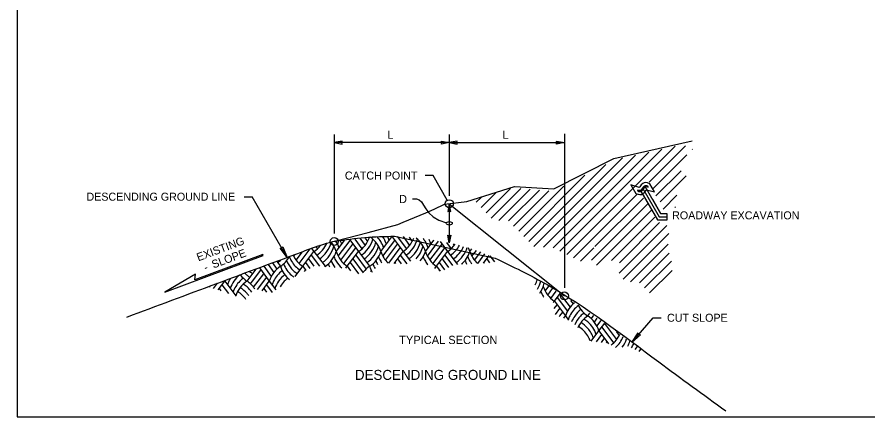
# Model space of a CAD drawing. Extents: x 99862 to 103151, y 100000 to 102076.
# Drawn here: x 99862 to 101562, y 100000 to 100799 of the extents above; entities that cross this region are included whole.
import ezdxf

# ---------------------------------------------------------------- set-up
doc = ezdxf.new("R2010")
doc.units = 0
for name, color, linetype in [('Level 1', 7, 'Continuous'), ('Level 14', 7, 'Continuous'), ('Level 15', 7, 'Continuous'), ('Level 16', 7, 'Continuous'), ('Level 17', 7, 'Continuous'), ('Level 20', 7, 'Continuous'), ('Level 3', 7, 'Continuous'), ('Level 4', 7, 'Continuous'), ('Level 5', 7, 'Continuous'), ('Level 60', 7, 'Continuous')]:
    doc.layers.add(name, color=color, linetype=linetype)

msp = doc.modelspace()

# ---------------------------------------------------------------- linework, layer by layer
at = {"layer": 'Level 1'}
msp.add_line((100616.2, 100361.1), (100817.1, 100317.4), dxfattribs=at)
msp.add_lwpolyline([(99862, 99999.5), (103151, 99999.5), (103151, 102075.5), (99862, 102075.5)], close=True, dxfattribs=at)
for points in [[(100498.7, 100351.1), (100557, 100358.6), (100616.2, 100361.1)], [(100817.1, 100317.4), (100921.2, 100264.2), (101144.4, 100109.7), (101278.1, 100011.9)]]:
    msp.add_spline(points, degree=3, dxfattribs=at)
at = {"layer": 'Level 14'}
msp.add_line((100652.4, 100435.5), (100660.4, 100435.5), dxfattribs=at)
for centre in [(100725.8, 100426.1), (100495.8, 100350.5)]:
    msp.add_circle(centre, 8, dxfattribs=at)
msp.add_ellipse((100725.8, 100386.9), major_axis=(-6, 0), ratio=0.57735, dxfattribs=at)
msp.add_open_spline([(100660.4, 100435.5), (100677.2, 100435.5), (100672.9, 100398.9), (100720.2, 100388.1)], degree=3, dxfattribs=at)
at = {"layer": 'Level 15'}
for p, q in [((100495.8, 100564.2), (100495.8, 100366.5)), ((100725.8, 100564.2), (100725.8, 100442.1)), ((100955.8, 100565.7), (100955.8, 100257.6)), ((100725.8, 100548.2), (100495.8, 100548.2)), ((100725.8, 100548.2), (100955.8, 100548.2)), ((100693.3, 100482.4), (100677.3, 100482.4)), ((100721.8, 100433), (100693.3, 100482.4)), ((101108.7, 100450.9), (101117.2, 100460.2)), ((101108.7, 100450.9), (101141.6, 100394)), ((101112.5, 100456.3), (101145, 100400)), ((100315.7, 100440.1), (100331.7, 100440.1)), ((100401.8, 100318.7), (100331.7, 100440.1)), ((100725.8, 100426.1), (100725.8, 100347.7)), ((101131.8, 100435), (101148.5, 100406)), ((101141.6, 100394), (101161, 100394)), ((101145, 100400), (101161, 100400)), ((101145, 100400), (101161, 100400)), ((101145, 100400), (101161, 100400)), ((101090.4, 100148.6), (101132.8, 100198)), ((101132.8, 100198), (101148.8, 100198))]:
    msp.add_line(p, q, dxfattribs=at)
for points in [[(100495.8, 100548.2), (100511.5, 100545.1), (100510.8, 100548.2), (100511.5, 100551.3)], [(100725.8, 100548.2), (100710.1, 100545.1), (100710.8, 100548.2), (100710.1, 100551.3)], [(100725.8, 100548.2), (100741.5, 100545.1), (100740.8, 100548.2), (100741.5, 100551.3)], [(100955.8, 100548.2), (100940.1, 100545.1), (100940.8, 100548.2), (100940.1, 100551.3)], [(100725.8, 100426.1), (100722.7, 100410.4), (100725.8, 100411.1), (100728.9, 100410.4)], [(100725.8, 100347.7), (100722.7, 100363.4), (100725.8, 100362.7), (100728.9, 100363.4)], [(100401.8, 100318.7), (100387.8, 100337), (100390.9, 100337.6), (100392.9, 100340)], [(101090.4, 100148.6), (101103.1, 100167.9), (101104.6, 100165.2), (101107.6, 100164)]]:
    msp.add_lwpolyline(points, close=True, dxfattribs=at)
msp.add_circle((100955.8, 100241.6), 8, dxfattribs=at)
at = {"layer": 'Level 16'}
for p, q in [((100725.8, 100426.1), (100955.8, 100241.6)), ((100633.5, 100389.1), (100678.7, 100407.9))]:
    msp.add_line(p, q, dxfattribs=at)
for points in [[(100678.7, 100407.9), (100695.8, 100415.1), (100716.2, 100424.9), (100761, 100430.7), (100856.2, 100460.7), (100934.4, 100455.5), (101054.4, 100516.8), (101210.8, 100552)], [(100499.2, 100351.5), (100563.5, 100368.4), (100622.8, 100384.6), (100633.5, 100389.1)]]:
    msp.add_lwpolyline(points, dxfattribs=at)
msp.add_spline([(100081.3, 100199.3), (100441.4, 100333.5), (100486.4, 100348.7), (100495.6, 100350.9), (100499.2, 100351.5)], degree=3, dxfattribs=at)
at = {"layer": 'Level 17'}
for p, q in [((100933, 100337.9), (101124.3, 100529.2)), ((100933, 100337.9), (101124.3, 100529.2)), ((100946.6, 100331.1), (101150.7, 100535.3)), ((100960.3, 100324.4), (101177.2, 100541.4)), ((101125.4, 100469.2), (101198, 100541.8)), ((101211.3, 100534.8), (101212, 100535.4)), ((100894.7, 100340.3), (101071.9, 100517.5)), ((100914, 100339.2), (101098, 100523.2)), ((101132.8, 100456.2), (101200.2, 100523.6)), ((100884.6, 100350.6), (101038.7, 100504.7)), ((100884.6, 100350.6), (101038.7, 100504.7)), ((101138.5, 100441.6), (101188.8, 100491.9)), ((100874.5, 100360.8), (100996.5, 100482.9)), ((101147.1, 100430), (101198.9, 100481.9)), ((100864.4, 100371.1), (100954.3, 100461)), ((100789.4, 100418.3), (100818.9, 100447.8)), ((100799.3, 100407.8), (100848.1, 100456.6)), ((100809.1, 100397.3), (100868.5, 100456.7)), ((100809.1, 100397.3), (100868.5, 100456.7)), ((100825, 100392.8), (100887.2, 100455)), ((100844.2, 100391.6), (100905.8, 100453.2)), ((100854.3, 100381.3), (100924.4, 100451.5)), ((100854.3, 100381.3), (100924.4, 100451.5)), ((100973.9, 100317.7), (101101.1, 100444.9)), ((101152.9, 100415.3), (101180.6, 100443)), ((100779.6, 100428.9), (100789.8, 100439)), ((100779.6, 100428.9), (100789.8, 100439)), ((101010.1, 100313.2), (101122.8, 100425.8)), ((101016.9, 100340.3), (101113.5, 100436.9)), ((101020.1, 100303.1), (101130, 100413)), ((101176.6, 100418.8), (101177.8, 100420)), ((101049.9, 100312.2), (101136.7, 100399)), ((101065.3, 100287.4), (101160.2, 100382.3)), ((101065.7, 100308), (101146, 100388.2)), ((101073, 100275), (101164.7, 100366.8)), ((101087.7, 100269.7), (101163.4, 100345.4)), ((100987.6, 100311), (101014.7, 100338.1)), ((101105.9, 100267.8), (101165.4, 100327.3)), ((101115.9, 100257.7), (101169.6, 100311.4)), ((101126, 100247.7), (101170.9, 100292.6))]:
    msp.add_line(p, q, dxfattribs=at)
at = {"layer": 'Level 20'}
for p, q in [((101113.5, 100459.8), (101111.2, 100456.3)), ((101113.5, 100459.8), (101111.2, 100456.3)), ((101115.4, 100461.3), (101113.5, 100459.8)), ((101115.4, 100461.3), (101113.5, 100459.8)), ((101114.3, 100456.7), (101115.7, 100458.7)), ((101114.3, 100456.7), (101115.7, 100458.7)), ((101117, 100461.9), (101115.4, 100461.3)), ((101117, 100461.9), (101115.4, 100461.3)), ((101115.7, 100458.7), (101116.8, 100459.7)), ((101115.7, 100458.7), (101116.8, 100459.7)), ((101116.8, 100459.7), (101118.2, 100460.1)), ((101116.8, 100459.7), (101118.2, 100460.1)), ((101118.6, 100462.1), (101117, 100461.9)), ((101118.6, 100462.1), (101117, 100461.9)), ((101118.2, 100460.1), (101119.8, 100460.2)), ((101118.2, 100460.1), (101119.8, 100460.2)), ((101120.3, 100461.8), (101118.6, 100462.1)), ((101120.3, 100461.8), (101118.6, 100462.1)), ((101119.8, 100460.2), (101123.4, 100459.3)), ((101119.8, 100460.2), (101123.4, 100459.3)), ((101122.3, 100461.1), (101120.3, 100461.8)), ((101122.3, 100461.1), (101120.3, 100461.8)), ((101123.4, 100459.3), (101122.3, 100461.1)), ((101123.4, 100459.3), (101122.3, 100461.1)), ((101104, 100452.6), (101101.7, 100453.4)), ((101101.7, 100453.4), (101102.8, 100451.5)), ((101104, 100452.6), (101101.7, 100453.4)), ((101101.7, 100453.4), (101102.8, 100451.5)), ((101102.8, 100451.5), (101104.6, 100450.8)), ((101102.8, 100451.5), (101104.6, 100450.8)), ((101105.7, 100452.4), (101104, 100452.6)), ((101105.7, 100452.4), (101104, 100452.6)), ((101104.6, 100450.8), (101106.4, 100450.5)), ((101104.6, 100450.8), (101106.4, 100450.5)), ((101107.1, 100452.5), (101105.7, 100452.4)), ((101107.1, 100452.5), (101105.7, 100452.4)), ((101106.4, 100450.5), (101108.1, 100450.7)), ((101106.4, 100450.5), (101108.1, 100450.7)), ((101108.3, 100453), (101107.1, 100452.5)), ((101108.3, 100453), (101107.1, 100452.5)), ((101108.1, 100450.7), (101109.7, 100451.4)), ((101108.1, 100450.7), (101109.7, 100451.4)), ((101109.8, 100454.3), (101108.3, 100453)), ((101109.8, 100454.3), (101108.3, 100453)), ((101109.7, 100451.4), (101111.8, 100453.1)), ((101109.7, 100451.4), (101111.8, 100453.1)), ((101111.2, 100456.3), (101109.8, 100454.3)), ((101111.2, 100456.3), (101109.8, 100454.3)), ((101111.8, 100453.1), (101114.3, 100456.7)), ((101111.8, 100453.1), (101114.3, 100456.7))]:
    msp.add_line(p, q, dxfattribs=at)
msp.add_lwpolyline([(101088.7, 100463.8), (101098.6, 100446.8), (101102.9, 100445), (101106.2, 100444.4), (101109.6, 100444.8), (101112.8, 100446.2), (101116.2, 100449), (101119.2, 100453.3), (101119.7, 100454), (101135.8, 100449.9), (101126.4, 100466), (101121.8, 100467.7), (101118.7, 100468.2), (101115.4, 100467.8), (101112.3, 100466.5), (101109, 100463.9), (101106.3, 100459.7), (101105.4, 100458.5), (101105.4, 100458.5)], close=True, dxfattribs=at)
at = {"layer": 'Level 3'}
msp.add_lwpolyline([(100353.2, 100324.6), (100217, 100273.9), (100218.9, 100285.1), (100157.6, 100249.1), (100354.1, 100322.3)], close=True, dxfattribs=at)
at = {"layer": 'Level 4'}
for p, q in [((100546.7, 100357.1), (100557.4, 100342.8)), ((100557.6, 100357.4), (100562.6, 100350.8)), ((100588.9, 100330.6), (100611, 100360.1)), ((100611.3, 100360.1), (100633.4, 100330.6)), ((100621.9, 100360.8), (100640.4, 100336.1)), ((100633.4, 100360.2), (100646.5, 100342.8)), ((100645.5, 100359), (100651.7, 100350.8)), ((100459.3, 100340), (100462.2, 100336.1)), ((100499.8, 100330.6), (100516.2, 100352.4)), ((100503.8, 100321.1), (100527.6, 100352.8)), ((100508.9, 100313.1), (100533.2, 100345.4)), ((100526.9, 100353.8), (100544.3, 100330.6)), ((100536.8, 100355.4), (100551.3, 100336.1)), ((100537.1, 100355.1), (100537.1, 100355)), ((100592.9, 100321.1), (100616.7, 100352.8)), ((100598, 100313.1), (100622.3, 100345.4)), ((100678, 100330.6), (100694.7, 100352.9)), ((100682, 100321.1), (100704.5, 100351.1)), ((100687.1, 100313.1), (100711.4, 100345.4)), ((100707.5, 100350.6), (100722.5, 100330.6)), ((100720.4, 100348.3), (100729.5, 100336.1)), ((100733.2, 100346), (100735.6, 100342.8)), ((100414.7, 100321.1), (100416.8, 100323.9)), ((100419.9, 100313.1), (100432.5, 100330)), ((100426, 100306.4), (100448, 100335.7)), ((100432.9, 100300.9), (100455.2, 100330.6)), ((100449.7, 100323.1), (100466.3, 100301)), ((100450.6, 100336.7), (100455.2, 100330.6)), ((100455.2, 100330.6), (100477.5, 100300.9)), ((100515.1, 100306.4), (100538.7, 100338)), ((100522, 100300.9), (100544.3, 100330.6)), ((100538.7, 100323.1), (100559.6, 100295.3)), ((100544.3, 100330.6), (100566.6, 100300.9)), ((100604.7, 100307.2), (100627.8, 100338)), ((100615.5, 100306.6), (100633.4, 100330.6)), ((100627.8, 100323.1), (100640.6, 100306.1)), ((100633.4, 100330.6), (100648.1, 100311)), ((100693.3, 100306.4), (100716.9, 100338)), ((100700.2, 100300.9), (100722.5, 100330.6)), ((100716.9, 100323.1), (100732.2, 100302.7)), ((100722.5, 100330.6), (100742, 100304.6)), ((100767.1, 100330.6), (100770.9, 100335.8)), ((100771.1, 100321.1), (100779.8, 100332.7)), ((100776.2, 100313.1), (100788.5, 100329.5)), ((100782.5, 100306.6), (100797, 100326)), ((100794, 100307.1), (100805.6, 100322.5)), ((100806.9, 100321.9), (100816, 100309.8)), ((100372.3, 100307.5), (100381.4, 100295.3)), ((100381, 100310.7), (100388.4, 100300.9)), ((100438.5, 100308.3), (100447.3, 100296.6)), ((100444.1, 100315.7), (100455.1, 100301)), ((100527.6, 100308.3), (100544.6, 100285.6)), ((100533.2, 100315.7), (100553.9, 100288.1)), ((100616.7, 100308.3), (100618, 100306.5)), ((100622.3, 100315.7), (100629.6, 100306)), ((100705.8, 100308.3), (100716.5, 100294.1)), ((100711.4, 100315.7), (100724.3, 100298.4)), ((100794.9, 100308.3), (100795.7, 100307.2)), ((100800.5, 100315.7), (100806.4, 100307.7)), ((100321.6, 100271.2), (100339.8, 100295.4)), ((100332.7, 100271.2), (100349.4, 100293.4)), ((100346.2, 100297.8), (100366.1, 100271.2)), ((100354.9, 100301), (100370.1, 100280.7)), ((100363.6, 100304.2), (100375.3, 100288.6)), ((100417.6, 100280.4), (100432.9, 100300.9)), ((100432.9, 100300.9), (100439.4, 100292.3)), ((100436.5, 100290.8), (100438.5, 100293.4)), ((100519.3, 100297.2), (100522, 100300.9)), ((100522, 100300.9), (100528.6, 100292.1)), ((100697, 100296.6), (100700.2, 100300.9)), ((100700.2, 100300.9), (100707.4, 100291.3)), ((100705.1, 100292.5), (100705.8, 100293.4)), ((100263.8, 100253.5), (100277, 100271.2)), ((100276.4, 100272), (100277, 100271.2)), ((100277, 100271.2), (100299.3, 100241.5)), ((100328.6, 100265.6), (100332.7, 100271.2)), ((100334.7, 100258.9), (100343.9, 100271.2)), ((100342.4, 100254.3), (100355, 100271.2)), ((100343.9, 100271.2), (100355, 100286)), ((100351.6, 100251.7), (100366.1, 100271.2)), ((100355, 100271.2), (100360.6, 100278.6)), ((100366.1, 100271.2), (100379.1, 100253.9)), ((100246.7, 100259.4), (100248.1, 100261.3)), ((100254.9, 100256.5), (100262.8, 100267)), ((100265.9, 100256.3), (100269.5, 100251.5)), ((100271.5, 100263.7), (100284.4, 100246.5)), ((100355, 100256.3), (100360.3, 100249.2)), ((100360.6, 100263.7), (100371.8, 100248.8)), ((100917.4, 100251.4), (100924.6, 100261)), ((100922.6, 100243.4), (100932.1, 100256.2)), ((100928.7, 100236.7), (100939.6, 100251.2)), ((100935.7, 100231.2), (100947, 100246.3)), ((100941.2, 100238.6), (100961.9, 100211)), ((100947.3, 100245.4), (100967.1, 100218.9)), ((100933.4, 100228.2), (100935.7, 100231.2)), ((100935.6, 100216.3), (100941.2, 100223.7)), ((100935.7, 100231.2), (100957.9, 100201.5)), ((100968.2, 100232.3), (100973.2, 100225.6)), ((100937.9, 100204.5), (100946.8, 100216.3)), ((100946.8, 100201.5), (100952.4, 100208.9)), ((101002.5, 100201.5), (101006.8, 100207.3)), ((100946.3, 100200.8), (100946.8, 100201.5)), ((100954.8, 100197.2), (100957.9, 100201.5)), ((100957.9, 100201.5), (100964.1, 100193.2)), ((101009.5, 100195.9), (101013.6, 100201.5)), ((101013.6, 100201.5), (101014.2, 100202.2)), ((101015.6, 100189.2), (101021.5, 100197.2)), ((101020.7, 100181.3), (101028.9, 100192.2)), ((101024.7, 100171.8), (101036.3, 100187.1)), ((101035.9, 100186.6), (101060.1, 100154.3)), ((101009.5, 100151.4), (101024.7, 100171.8)), ((101024.7, 100171.8), (101044.1, 100146)), ((101030.3, 100179.2), (101054, 100147.6)), ((101057.6, 100172.5), (101058.1, 100171.8)), ((101058.9, 100170.8), (101065.3, 100162.3)), ((101019.6, 100150.1), (101030.3, 100164.4)), ((101029.8, 100148.8), (101035.9, 100156.9)), ((101040, 100147.6), (101041.5, 100149.5)), ((101091.6, 100142.1), (101094.3, 100145.7)), ((101097, 100134.4), (101101.5, 100140.5)), ((101105.4, 100130.8), (101108.8, 100135.4))]:
    msp.add_line(p, q, dxfattribs=at)
for centre, start, end in [((100512.9, 100377.3), 303.9036, 340.5936), ((100535.2, 100313.5), 17.6434, 53.8984), ((100540.7, 100320.9), 31.3316, 42.8625), ((100546.3, 100328.3), 17.6434, 34.894), ((100551.9, 100335.7), 17.6434, 25.603), ((100602, 100377.3), 303.9036, 339.4364), ((100624.2, 100313.5), 17.6434, 50.9572), ((100629.8, 100320.9), 31.3316, 39.1061), ((100423.8, 100377.3), 303.9036, 322.3781), ((100429.4, 100369.9), 303.9036, 335.6813), ((100434.9, 100362.5), 303.9036, 346.3086), ((100440.5, 100355.1), 303.9036, 345.7713), ((100446.1, 100313.5), 17.6434, 39.2841), ((100451.6, 100320.9), 17.6434, 32.1834), ((100451.6, 100320.9), 31.3316, 31.4695), ((100457.2, 100328.3), 17.6434, 24.2252), ((100518.4, 100369.9), 303.9036, 345.0113), ((100524, 100362.5), 303.9036, 346.3199), ((100529.6, 100355.1), 303.9036, 345.7713), ((100540.7, 100320.9), 17.6434, 31.3317), ((100607.5, 100369.9), 303.9036, 345.0113), ((100613.1, 100362.5), 303.9036, 346.3199), ((100618.7, 100355.1), 316.0724, 345.7713), ((100629.8, 100320.9), 17.6434, 31.3317), ((100635.4, 100328.3), 17.6434, 27.7275), ((100640.9, 100335.7), 17.6434, 17.6828), ((100691.1, 100377.3), 303.9036, 325.2547), ((100696.6, 100369.9), 303.9036, 331.4569), ((100702.2, 100362.5), 303.9036, 337.2506), ((100707.8, 100355.1), 303.9036, 342.9746), ((100464.4, 100347.6), 206.0688, 236.0964), ((100446.1, 100347.6), 303.9036, 342.3566), ((100553.5, 100347.6), 197.6435, 236.0964), ((100535.2, 100347.6), 303.9036, 342.3566), ((100642.6, 100347.6), 197.6435, 225.8164), ((100624.2, 100347.6), 320.3496, 342.3566), ((100731.7, 100347.6), 197.6435, 236.0964), ((100713.3, 100347.6), 310.7977, 342.3566), ((100713.3, 100313.5), 17.6434, 25.6266), ((100820.8, 100347.6), 197.6435, 226.8096), ((100351.4, 100355.1), 303.9036, 313.2068), ((100357, 100347.6), 303.9036, 331.007), ((100447.7, 100325.4), 200.2432, 228.9599), ((100453.3, 100332.8), 201.4344, 220.9416), ((100458.8, 100340.2), 200.8778, 211.332), ((100458.8, 100340.2), 211.3319, 236.0964), ((100536.8, 100325.4), 200.2432, 207.2958), ((100542.3, 100332.8), 201.4344, 217.1501), ((100547.9, 100340.2), 200.8778, 211.332), ((100547.9, 100340.2), 211.3319, 228.8141), ((100625.9, 100325.4), 200.2432, 211.0971), ((100631.4, 100332.8), 201.4344, 210.0752), ((100637, 100340.2), 200.8778, 211.332), ((100637, 100340.2), 211.3319, 215.0934), ((100726.1, 100340.2), 200.8778, 211.332), ((100726.1, 100340.2), 211.3319, 220.324), ((100804.1, 100325.4), 200.2432, 201.1433), ((100809.6, 100332.8), 201.4344, 208.9936), ((100815.2, 100340.2), 200.8778, 211.332), ((100815.2, 100340.2), 211.3319, 217.4176), ((100364.2, 100332.8), 228.4448, 236.0964), ((100369.7, 100340.2), 234.4347, 236.0964), ((100419.8, 100254.1), 123.9036, 162.3566), ((100425.4, 100246.7), 126.3063, 154.2266), ((100442.1, 100317.9), 197.6434, 230.7454), ((100453.3, 100332.8), 220.9415, 236.0964), ((100508.9, 100254.1), 123.9036, 125.0153), ((100531.2, 100317.9), 197.6434, 198.3911), ((100598, 100254.1), 123.9036, 141.3531), ((100620.3, 100317.9), 197.6434, 210.7756), ((100603.6, 100246.7), 126.4534, 129.4152), ((100330.8, 100254.1), 160.9915, 162.3566), ((100336.3, 100246.7), 154.2265, 162.3566), ((100336.3, 100246.7), 148.0142, 154.2266), ((100341.9, 100239.2), 145.491, 162.3566), ((100347.5, 100231.8), 135.7127, 162.3566), ((100341.9, 100239.2), 128.7686, 145.4911), ((100353, 100224.4), 123.9036, 162.3566), ((100347.5, 100231.8), 126.331, 135.7128), ((100353, 100317.9), 217.3234, 236.0964), ((100358.6, 100325.4), 222.7713, 228.9599), ((100358.6, 100325.4), 228.9599, 236.0964), ((100290.1, 100224.4), 33.9594, 56.0963), ((100425.4, 100246.7), 154.2265, 162.3566), ((100431, 100239.2), 145.491, 162.3566), ((100431, 100239.2), 127.1006, 145.4911), ((100436.5, 100231.8), 135.7127, 149.866), ((100436.5, 100231.8), 126.331, 135.7128), ((100447.7, 100325.4), 228.9599, 235.023), ((100848.5, 100292.8), 329.3968, 340.9198), ((100854.1, 100285.4), 327.9213, 345.4615), ((100279, 100209.5), 40.9413, 59.3021), ((100284.6, 100217), 48.9597, 58.5465), ((100284.6, 100217), 34.462, 48.9597), ((100859.7, 100278), 326.4665, 349.0114), ((100967.1, 100278), 197.9705, 236.0964), ((100267.9, 100194.7), 55.9832, 56.0964), ((100245.6, 100258.5), 342.3268, 342.3566), ((100273.4, 100202.1), 35.4646, 58.4874), ((100279, 100209.5), 34.9633, 40.9414), ((100961.5, 100270.5), 200.8778, 211.332), ((100961.5, 100270.5), 211.3319, 214.1044), ((101011.6, 100184.4), 129.3535, 162.3566), ((101017.2, 100177), 126.3063, 154.2266), ((101033.9, 100248.3), 205.5493, 236.0964), ((101022.8, 100169.5), 127.1006, 145.4911), ((101028.3, 100162.1), 126.331, 135.7128), ((101017.2, 100177), 154.2265, 162.3566), ((101022.8, 100169.5), 145.491, 158.6313), ((101028.3, 100162.1), 135.7127, 157.1828), ((101033.9, 100154.7), 123.9036, 155.7492), ((100959.9, 100139.8), 40.9413, 59.3021), ((100965.5, 100147.3), 48.9597, 58.5465), ((100971, 100154.7), 17.6434, 56.0963), ((100965.5, 100147.3), 17.6434, 48.9597), ((100954.3, 100132.4), 31.3316, 58.4874), ((100959.9, 100139.8), 17.6434, 40.9414), ((100954.3, 100132.4), 19.9526, 31.3317), ((101015.6, 100188.9), 306.2544, 335.215), ((101021.1, 100181.4), 310.5682, 338.1541), ((101026.7, 100174), 321.5302, 341.1301), ((101032.3, 100166.6), 333.1711, 344.1527), ((101037.9, 100159.2), 337.6177, 342.3566)]:
    msp.add_arc(centre, 56.4, start, end, dxfattribs=at)
at = {"layer": 'Level 5'}
msp.add_lwpolyline([(101117.2, 100460.2), (101108.7, 100450.9), (101141.6, 100394), (101161, 100394), (101161, 100406), (101148.5, 100406), (101117.2, 100460.2)], dxfattribs=at)
at = {"layer": 'Level 60'}
msp.add_line((99862, 99999.5), (99862, 99999.5), dxfattribs=at)
msp.add_line((99862, 99999.5), (99862, 99999.5), dxfattribs=at)
msp.add_line((99862, 99999.5), (99862, 99999.5), dxfattribs=at)

# ---------------------------------------------------------------- texts
at = {"layer": 'Level 20'}
for s, height, p in [('L ', 16.5, (100601.9, 100555.9)), ('L ', 16.5, (100831.9, 100555.9)), ('CATCH POINT', 16, (100517.1, 100474.4)), ('DESCENDING GROUND LINE', 16, (100000.7, 100432.1)), ('D', 16.5, (100625.2, 100427.2)), ('ROADWAY EXCAVATION', 16, (101171, 100394.8)), ('CUT SLOPE', 16, (101160.8, 100190)), ('TYPICAL SECTION', 16.5, (100625.7, 100145.4)), ('DESCENDING GROUND LINE', 20, (100537.1, 100073.7))]:
    msp.add_text(s, height=height, dxfattribs=at).set_placement(p)
for s, p in [('EXISTING', (100224.4, 100310.7)), (' SLOPE', (100249, 100294.3)), ('-', (100238.6, 100290.4))]:
    msp.add_text(s, height=16, rotation=20.43, dxfattribs=at).set_placement(p)

doc.saveas('drawing.dxf')
